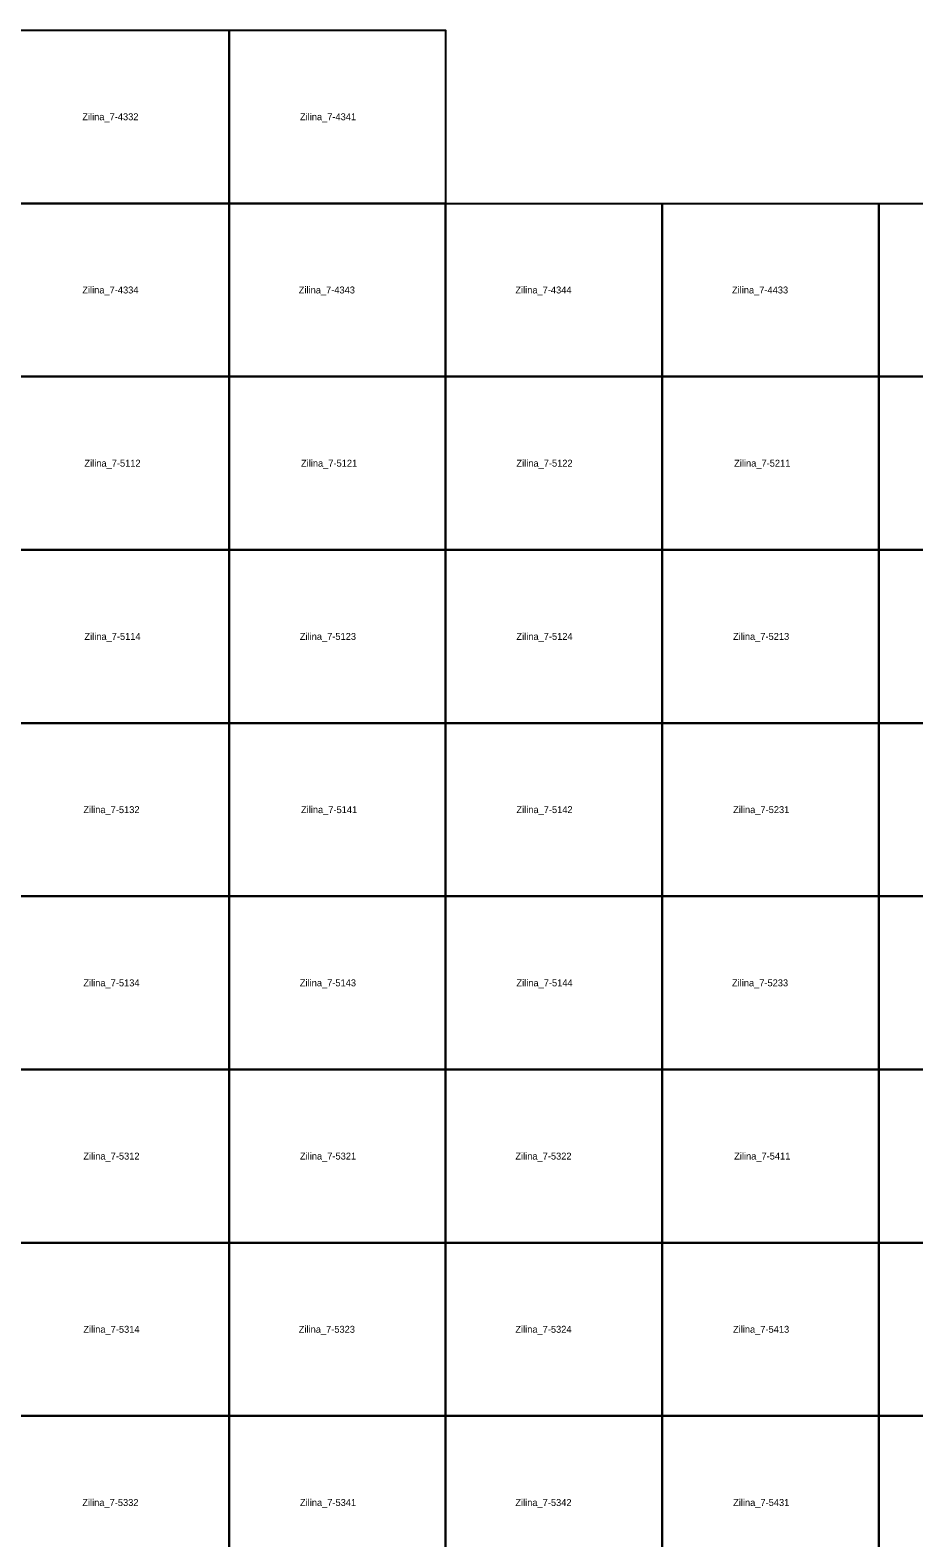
# Model space of a CAD drawing. Extents: x -445938 to -437812, y -1177250 to -1169500.
# Drawn here: x -444662 to -443387, y -1171676 to -1169500 of the extents above; entities that cross this region are included whole.
import ezdxf

# ---------------------------------------------------------------- set-up
doc = ezdxf.new("R2010")
doc.units = 0
for name, color, linetype in [('Vrstva 1', 7, 'Continuous'), ('Vrstva 4', 7, 'Continuous'), ('Vrstva 6', 7, 'Continuous')]:
    doc.layers.add(name, color=color, linetype=linetype)

msp = doc.modelspace()

# ---------------------------------------------------------------- linework, layer by layer
at = {"layer": 'Vrstva 1'}
msp.add_lwpolyline([(-440625, -1175500), (-441562.5, -1175500), (-441562.5, -1175000), (-442812.5, -1175000), (-442812.5, -1175750), (-443437.5, -1175750), (-443437.5, -1177250), (-445000, -1177250), (-445000, -1175500), (-445312.5, -1175500), (-445312.5, -1173750), (-445937.5, -1173750), (-445937.5, -1172250), (-445625, -1172250), (-445625, -1169500), (-444062.5, -1169500), (-444062.5, -1169750), (-441562.5, -1169750), (-441562.5, -1170000), (-440000, -1170000)], dxfattribs=at)
at = {"layer": 'Vrstva 4'}
for points in [[(-444375, -1169500), (-444375, -1169750), (-444687.5, -1169750), (-444687.5, -1169500)], [(-444062.5, -1169500), (-444062.5, -1169750), (-444375, -1169750), (-444375, -1169500)], [(-444375, -1169750), (-444375, -1170000), (-444687.5, -1170000), (-444687.5, -1169750)], [(-444062.5, -1169750), (-444062.5, -1170000), (-444375, -1170000), (-444375, -1169750)], [(-443750, -1169750), (-443750, -1170000), (-444062.5, -1170000), (-444062.5, -1169750)], [(-443437.5, -1169750), (-443437.5, -1170000), (-443750, -1170000), (-443750, -1169750)], [(-443125, -1169750), (-443125, -1170000), (-443437.5, -1170000), (-443437.5, -1169750)], [(-444375, -1170000), (-444375, -1170250), (-444687.5, -1170250), (-444687.5, -1170000)], [(-444062.5, -1170000), (-444062.5, -1170250), (-444375, -1170250), (-444375, -1170000)], [(-443750, -1170000), (-443750, -1170250), (-444062.5, -1170250), (-444062.5, -1170000)], [(-443437.5, -1170000), (-443437.5, -1170250), (-443750, -1170250), (-443750, -1170000)], [(-443125, -1170000), (-443125, -1170250), (-443437.5, -1170250), (-443437.5, -1170000)], [(-444375, -1170250), (-444375, -1170500), (-444687.5, -1170500), (-444687.5, -1170250)], [(-444062.5, -1170250), (-444062.5, -1170500), (-444375, -1170500), (-444375, -1170250)], [(-443750, -1170250), (-443750, -1170500), (-444062.5, -1170500), (-444062.5, -1170250)], [(-443437.5, -1170250), (-443437.5, -1170500), (-443750, -1170500), (-443750, -1170250)], [(-443125, -1170250), (-443125, -1170500), (-443437.5, -1170500), (-443437.5, -1170250)], [(-444375, -1170500), (-444375, -1170750), (-444687.5, -1170750), (-444687.5, -1170500)], [(-444062.5, -1170500), (-444062.5, -1170750), (-444375, -1170750), (-444375, -1170500)], [(-443750, -1170500), (-443750, -1170750), (-444062.5, -1170750), (-444062.5, -1170500)], [(-443437.5, -1170500), (-443437.5, -1170750), (-443750, -1170750), (-443750, -1170500)], [(-443125, -1170500), (-443125, -1170750), (-443437.5, -1170750), (-443437.5, -1170500)], [(-444375, -1170750), (-444375, -1171000), (-444687.5, -1171000), (-444687.5, -1170750)], [(-444062.5, -1170750), (-444062.5, -1171000), (-444375, -1171000), (-444375, -1170750)], [(-443750, -1170750), (-443750, -1171000), (-444062.5, -1171000), (-444062.5, -1170750)], [(-443437.5, -1170750), (-443437.5, -1171000), (-443750, -1171000), (-443750, -1170750)], [(-443125, -1170750), (-443125, -1171000), (-443437.5, -1171000), (-443437.5, -1170750)], [(-444375, -1171000), (-444375, -1171250), (-444687.5, -1171250), (-444687.5, -1171000)], [(-444062.5, -1171000), (-444062.5, -1171250), (-444375, -1171250), (-444375, -1171000)], [(-443750, -1171000), (-443750, -1171250), (-444062.5, -1171250), (-444062.5, -1171000)], [(-443437.5, -1171000), (-443437.5, -1171250), (-443750, -1171250), (-443750, -1171000)], [(-443125, -1171000), (-443125, -1171250), (-443437.5, -1171250), (-443437.5, -1171000)], [(-444375, -1171250), (-444375, -1171500), (-444687.5, -1171500), (-444687.5, -1171250)], [(-444062.5, -1171250), (-444062.5, -1171500), (-444375, -1171500), (-444375, -1171250)], [(-443750, -1171250), (-443750, -1171500), (-444062.5, -1171500), (-444062.5, -1171250)], [(-443437.5, -1171250), (-443437.5, -1171500), (-443750, -1171500), (-443750, -1171250)], [(-443125, -1171250), (-443125, -1171500), (-443437.5, -1171500), (-443437.5, -1171250)], [(-444375, -1171500), (-444375, -1171750), (-444687.5, -1171750), (-444687.5, -1171500)], [(-444062.5, -1171500), (-444062.5, -1171750), (-444375, -1171750), (-444375, -1171500)], [(-443750, -1171500), (-443750, -1171750), (-444062.5, -1171750), (-444062.5, -1171500)], [(-443437.5, -1171500), (-443437.5, -1171750), (-443750, -1171750), (-443750, -1171500)], [(-443125, -1171500), (-443125, -1171750), (-443437.5, -1171750), (-443437.5, -1171500)]]:
    msp.add_lwpolyline(points, close=True, dxfattribs=at)

# ---------------------------------------------------------------- texts
at = {"layer": 'Vrstva 6'}
for s, p in [('Zilina_7-4332', (-444586.756, -1169630)), ('Zilina_7-4341', (-444272.721, -1169630)), ('Zilina_7-4334', (-444586.756, -1169880)), ('Zilina_7-4343', (-444274.414, -1169880)), ('Zilina_7-4344', (-443961.914, -1169880)), ('Zilina_7-4433', (-443649.414, -1169880)), ('Zilina_7-5112', (-444583.686, -1170130)), ('Zilina_7-5121', (-444271.186, -1170130)), ('Zilina_7-5122', (-443960.379, -1170130)), ('Zilina_7-5211', (-443646.186, -1170130)), ('Zilina_7-5114', (-444583.686, -1170380)), ('Zilina_7-5123', (-444272.879, -1170380)), ('Zilina_7-5124', (-443960.379, -1170380)), ('Zilina_7-5213', (-443647.879, -1170380)), ('Zilina_7-5132', (-444585.222, -1170630)), ('Zilina_7-5141', (-444271.186, -1170630)), ('Zilina_7-5142', (-443960.379, -1170630)), ('Zilina_7-5231', (-443647.721, -1170630)), ('Zilina_7-5134', (-444585.222, -1170880)), ('Zilina_7-5143', (-444272.879, -1170880)), ('Zilina_7-5144', (-443960.379, -1170880)), ('Zilina_7-5233', (-443649.414, -1170880)), ('Zilina_7-5312', (-444585.222, -1171130)), ('Zilina_7-5321', (-444272.721, -1171130)), ('Zilina_7-5322', (-443961.914, -1171130)), ('Zilina_7-5411', (-443646.186, -1171130)), ('Zilina_7-5314', (-444585.222, -1171380)), ('Zilina_7-5323', (-444274.414, -1171380)), ('Zilina_7-5324', (-443961.914, -1171380)), ('Zilina_7-5413', (-443647.879, -1171380)), ('Zilina_7-5332', (-444586.756, -1171630)), ('Zilina_7-5341', (-444272.721, -1171630)), ('Zilina_7-5342', (-443961.914, -1171630)), ('Zilina_7-5431', (-443647.721, -1171630))]:
    msp.add_text(s, height=10, dxfattribs=at).set_placement(p)

doc.saveas('drawing.dxf')
